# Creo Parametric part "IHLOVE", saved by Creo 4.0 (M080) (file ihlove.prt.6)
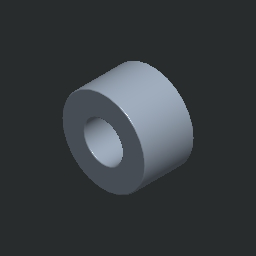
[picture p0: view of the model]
Units: Custom; MM, KILOGRAM, SECS
Materials in the file: OCEL_N

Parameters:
  MFG_WP_MATERIAL = "RO7"
  NAZOV = "IHLOVE"
  PTC_MATERIAL_NAME = "OCEL_N"

Other parameters: HMOTNOST, HUSTOTA

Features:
  1. round

Named dimensions: velke_D

Layers: 1, 2, 3, 4, 5, 6, 7, 8, 9, 10, 11, 12, 13, 14, 15, 16, 17, 18, 19, 20, 21, 22, 23, 24, 25, 26, 27, 28, 29, 30, 31, 32

Family table entries: GENERIC, LOZISKO_NA4900, IHLOVE, value(d_val), 2/6, 2/*, value(i_val), LOZISKO_NA4901, IHLOVE, !/(, 2/8, 2/*, LOZISKO_NA4902, IHLOVE, !/., 2/<, 2/*, LOZISKO_NA4903, IHLOVE, !/1, 2/>, 2/*, LOZISKO_NA4904, IHLOVE, !/4, 2/1, LOZISKO_NA49_22, IHLOVE, !/6, 2/1, LOZISKO_NA4905, IHLOVE, !/9, 2/E, 2/1, LOZISKO_NA49_28, IHLOVE, !/<, 2/1, LOZISKO_NA4906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

Surfaces: 8 torus, 2 plane, 2 cylinder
